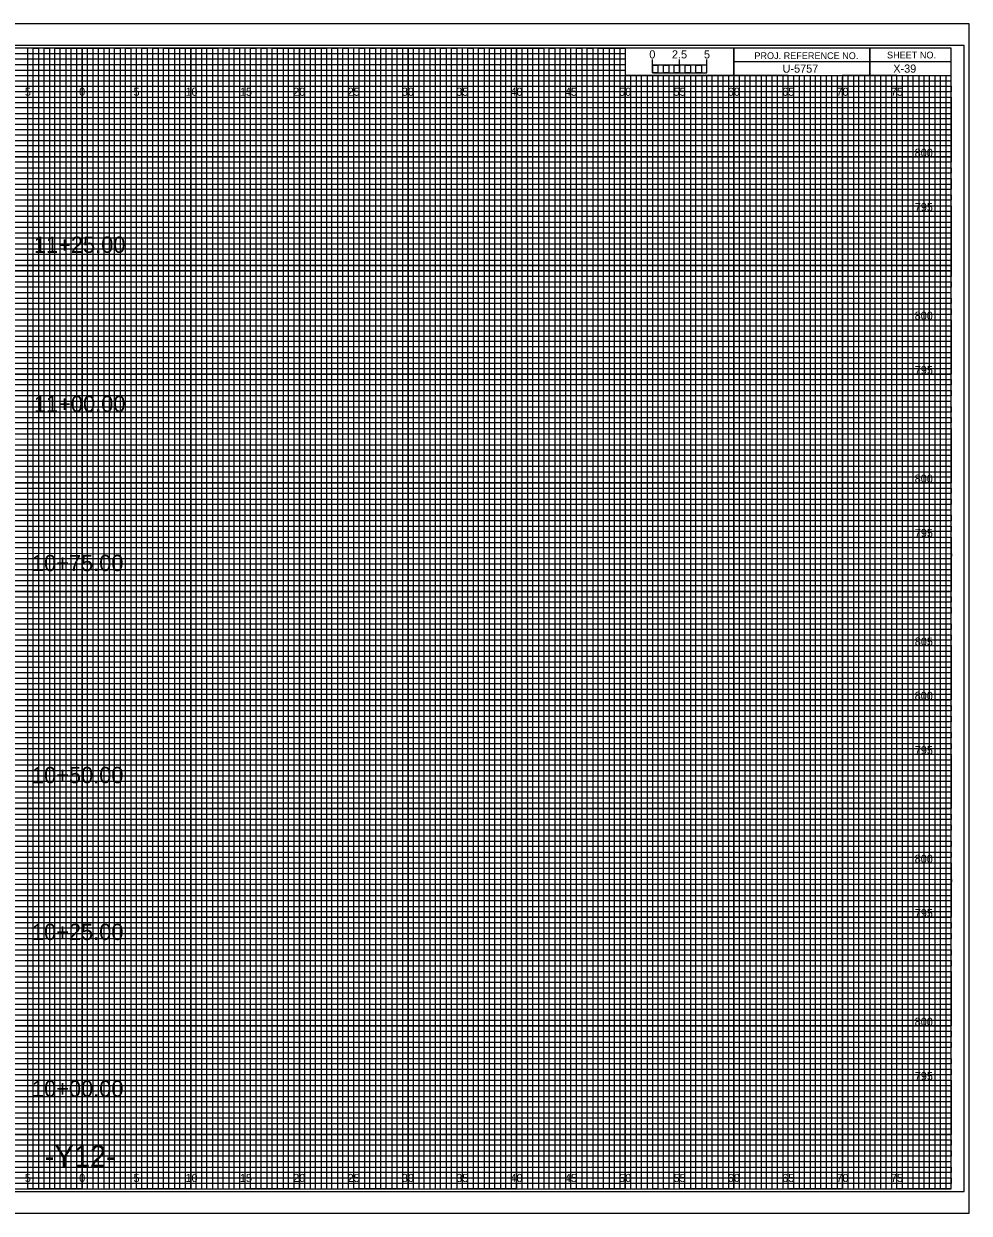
# Model space of a CAD drawing. Extents: x -7 to 162, y -2 to 107.
# Drawn here: x 74.6 to 161.7, y -2.3 to 107.3 of the extents above; entities that cross this region are included whole.
import ezdxf

# ---------------------------------------------------------------- set-up
doc = ezdxf.new("R2010")
doc.units = 0
for name, color, linetype in [('Exist Cross Section Cell', 7, 'Continuous'), ('Exist XS Center Line Elevation Label', 7, 'Continuous'), ('Prop CMT Pvmt Course 2 Wedge', 7, 'Continuous'), ('Prop CMT Shld Paved Course 3', 7, 'Continuous'), ('Prop XS Alignment Label', 7, 'Continuous'), ('Prop XS Bar Scale Labels', 7, 'Continuous'), ('Prop XS Elevation Labels', 7, 'Continuous'), ('Prop XS Hydro Elevations', 7, 'Continuous'), ('Prop XS Project Number', 7, 'Continuous'), ('Prop XS SE Text', 7, 'Continuous'), ('Prop XS Sheet Number', 7, 'Continuous'), ('Prop XS Side Slope Text', 7, 'Continuous'), ('Prop XS Station Labels', 7, 'Continuous'), ('Sheet Cross Section Grid Minor 2 CELL', 7, 'Continuous'), ('Sheet Cross Section Scale CELL', 7, 'Continuous'), ('Sheet DOT Grid CELL', 7, 'Continuous'), ('Sheet Plot Border Inside CELL', 7, 'Continuous')]:
    doc.layers.add(name, color=color, linetype=linetype)

msp = doc.modelspace()

# ---------------------------------------------------------------- linework, layer by layer
at = {"layer": 'Exist Cross Section Cell'}
for p, q in [((75, 105), (70, 105)), ((75, 0), (75, 105)), ((85, 105), (80, 105)), ((80, 105), (80, 0)), ((85, 0), (85, 105)), ((95, 105), (90, 105)), ((90, 105), (90, 0)), ((95, 0), (95, 105)), ((105, 105), (100, 105)), ((100, 105), (100, 0)), ((105, 0), (105, 105)), ((115, 105), (110, 105)), ((110, 105), (110, 0)), ((115, 0), (115, 105)), ((125, 105), (120, 105)), ((120, 105), (120, 0)), ((125, 0), (125, 105)), ((130, 105), (130, 0)), ((135, 0), (135, 102.5)), ((145, 102.5), (140, 102.5)), ((140, 102.5), (140, 0)), ((145, 0), (145, 102.5)), ((155, 102.5), (150, 102.5)), ((150, 102.5), (150, 0)), ((155, 0), (155, 102.5)), ((80, 0), (75, 0)), ((90, 0), (85, 0)), ((100, 0), (95, 0)), ((110, 0), (105, 0)), ((120, 0), (115, 0)), ((130, 0), (125, 0)), ((140, 0), (135, 0)), ((150, 0), (145, 0)), ((160, 0), (155, 0)), ((160, 0), (160, 0))]:
    msp.add_line(p, q, dxfattribs=at)
for points in [[(0, 100), (160, 100), (160, 95), (0, 95)], [(0, 90), (160, 90), (160, 85), (0, 85)], [(0, 80), (160, 80), (160, 75), (0, 75)], [(0, 70), (160, 70), (160, 65), (0, 65)], [(0, 60), (160, 60), (160, 55), (0, 55)], [(0, 50), (160, 50), (160, 45), (0, 45)], [(0, 40), (160, 40), (160, 35), (0, 35)], [(0, 30), (160, 30), (160, 25), (0, 25)], [(0, 20), (160, 20), (160, 15), (0, 15)], [(0, 10), (160, 10), (160, 5), (0, 5)]]:
    msp.add_lwpolyline(points, dxfattribs=at)
at = {"layer": 'Exist XS Center Line Elevation Label'}
for points in [[(72.5, 0), (77.5, 0), (77.5, 105), (82.5, 105), (82.5, 0), (87.5, 0), (87.5, 105), (92.5, 105), (92.5, 0), (97.5, 0), (97.5, 105), (102.5, 105), (102.5, 0), (107.5, 0), (107.5, 105), (112.5, 105), (112.5, 0), (117.5, 0), (117.5, 105), (122.5, 105), (122.5, 0), (127.5, 0), (127.5, 105), (129.97, 105), (130, 105), (130, 102.5), (132.5, 102.5), (132.5, 0), (137.5, 0), (137.5, 102.5), (142.5, 102.5), (142.5, 0), (147.5, 0), (147.5, 102.5), (152.5, 102.5), (152.5, 0), (157.5, 0), (157.5, 102.5)], [(0, 102.5), (137.5, 102.5)], [(0, 92.5), (160, 92.5), (160, 97.5), (0, 97.5)], [(0, 82.5), (160, 82.5), (160, 87.5), (0, 87.5)], [(0, 72.5), (160, 72.5), (160, 77.5), (0, 77.5)], [(0, 62.5), (160, 62.5), (160, 67.5), (0, 67.5)], [(0, 52.5), (160, 52.5), (160, 57.5), (0, 57.5)], [(0, 42.5), (160, 42.5), (160, 47.5), (0, 47.5)], [(0, 32.5), (160, 32.5), (160, 37.5), (0, 37.5)], [(0, 22.5), (160, 22.5), (160, 27.5), (0, 27.5)], [(0, 12.5), (160, 12.5), (160, 17.5), (0, 17.5)], [(0, 2.5), (160, 2.5), (160, 7.5), (0, 7.5)]]:
    msp.add_lwpolyline(points, dxfattribs=at)
at = {"layer": 'Prop CMT Pvmt Course 2 Wedge'}
for p, q in [((161.65, 107.25), (-6.7, 107.25)), ((-6.7, -2.25), (161.65, -2.25))]:
    msp.add_line(p, q, dxfattribs=at)
at = {"layer": 'Prop CMT Shld Paved Course 3'}
msp.add_lwpolyline([(-6.7, -2.25), (161.65, -2.25), (161.65, 107.25), (-6.7, 107.25)], close=True, dxfattribs=at)
at = {"layer": 'Prop XS Hydro Elevations'}
for p, q in [((152.5, 105), (152.5, 102.5)), ((152.5, 102.5), (152.5, 105)), ((160, 103.75), (140, 103.75)), ((140, 103.75), (140, 102.5)), ((140, 102.5), (160, 102.5))]:
    msp.add_line(p, q, dxfattribs=at)
for points in [[(160, 105), (0, 105), (0, 0), (160, 0)], [(140, 105), (130, 105), (130, 102.52), (140, 102.52)], [(160, 105), (140, 105), (140, 102.5), (160, 102.5)]]:
    msp.add_lwpolyline(points, close=True, dxfattribs=at)
at = {"layer": 'Prop XS Side Slope Text'}
for p, q in [((0, 104.5), (130, 104.5)), ((130, 104.5), (130, 103.99)), ((130, 103.99), (0, 103.99)), ((0, 103.5), (130, 103.5)), ((130, 102.95), (0, 102.95)), ((130, 103.5), (130, 102.95)), ((0, 102), (160, 102))]:
    msp.add_line(p, q, dxfattribs=at)
for points in [[(0, 101.5), (135, 101.5), (160, 101.5), (160, 101), (0, 101)], [(0, 100.5), (160, 100.5), (160, 99.5), (0, 99.5)], [(0, 99), (160, 99), (160, 98.5), (0, 98.49)], [(0, 98), (160, 98), (160, 97), (0, 97)], [(0, 96.5), (160, 96.5), (160, 96), (0, 96)], [(0, 95.5), (160, 95.5), (160, 94.5), (0, 94.5)], [(0, 94), (160, 94), (160, 93.5), (0, 93.5)], [(0, 93), (160, 93), (160, 92), (0, 92)], [(0, 91.5), (160, 91.5), (160, 91), (0, 91)], [(0, 90.5), (160, 90.5), (160, 89.5), (0, 89.5)], [(0, 89), (160, 89), (160, 88.5), (0, 88.5)], [(0, 88), (160, 88), (160, 86.98), (160, 86.5), (160, 86), (0, 86)], [(0, 87), (160, 87), (160, 86.5), (0, 86.5)], [(0, 85.5), (160, 85.5), (160, 84.5), (0, 84.52)], [(0, 84.52), (160, 84.5), (160, 84), (0, 84)], [(0, 83.5), (160, 83.5), (160, 83), (0, 83)], [(0, 82), (160, 82), (160, 81.5), (0, 81.5)], [(0, 81), (160, 81), (160, 80.5), (0, 80.5)], [(-0.04, 79.45), (160, 79.45), (160, 78.94), (-0.04, 78.94)], [(0, 78.5), (160, 78.5), (160, 78), (0, 78)], [(0, 77), (160, 77), (160, 76.5), (0, 76.5)], [(0, 76), (160, 76), (160, 75.5), (0, 75.5)], [(0, 74.5), (160, 74.5), (160, 74), (0, 74)], [(0, 73.5), (160, 73.5), (160, 73), (0, 73)], [(0, 72), (160, 72), (160, 71.5), (0, 71.5)], [(0, 71), (160, 71), (160, 70.5), (0, 70.5)], [(0, 69.5), (160, 69.5), (160, 68.99), (0, 69)], [(0, 68.5), (160, 68.5), (160, 68), (0, 68)], [(0, 67), (160, 67), (160, 66.5), (0, 66.5)], [(0, 66), (160, 66), (160, 65.5), (0, 65.5)], [(0, 64.5), (160, 64.5), (160, 64), (0, 64)], [(0, 63.5), (160, 63.5), (160, 63), (0, 63)], [(0, 62), (160, 62), (160, 61.5), (0, 61.5)], [(0, 61), (160, 61), (160, 60.5), (0, 60.5)], [(0, 59.5), (160, 59.5), (160, 59), (0, 59)], [(0, 58.5), (160.03, 58.45), (160, 58), (0, 58)], [(0, 57), (160, 57), (160, 56.5), (0, 56.5)], [(0, 56), (160, 56), (160, 55.5), (0, 55.5)], [(0, 54.5), (160, 54.5), (160, 54), (0, 54)], [(0, 53.5), (160, 53.5), (160, 53), (0, 53)], [(0, 52), (160, 52), (160, 51.5), (0, 51.5)], [(0, 51), (160, 51), (160, 50.5), (0, 50.5)], [(0, 49.5), (160, 49.5), (160, 49), (0, 49)], [(0, 48.5), (160, 48.5), (160, 48), (0, 48)], [(0, 47), (160, 47), (160, 46.5), (0, 46.5)], [(0, 46), (160, 46), (160, 45.5), (0, 45.5)], [(0, 44.5), (160, 44.5), (160, 44), (0, 44)], [(0, 43.5), (160, 43.5), (160, 43), (0, 43)], [(0, 42), (160, 42), (160, 41.5), (0, 41.5)], [(0, 41), (160, 41), (160, 40.5), (0, 40.5)], [(0, 39.5), (160, 39.5), (160, 38.99), (0, 39)], [(0, 38.5), (160, 38.5), (160, 38), (0, 38)], [(0, 37), (160, 37), (160, 36.5), (0, 36.5)], [(0, 36), (160, 36), (160, 35.5), (0, 35.5)], [(0, 34.5), (160, 34.5), (160, 34), (0, 34)], [(0, 33.5), (160, 33.5), (160, 33), (0, 33)], [(0, 32), (160, 32), (160, 31.5), (0, 31.5)], [(0, 31), (160, 31), (160, 30.5), (0, 30.5)], [(0, 29.5), (160, 29.5), (160, 29), (0, 29)], [(0, 28.5), (160.03, 28.46), (160, 28), (0, 28)], [(0, 27), (160, 27), (160, 26.5), (0, 26.5)], [(0, 26), (160, 26), (160, 25.5), (0, 25.5)], [(0, 24.5), (160, 24.5), (160, 24), (0, 24)], [(0, 23.5), (160, 23.5), (160, 23), (0, 23)], [(0, 22), (160, 22), (160, 21.5), (0, 21.5)], [(0, 21), (160, 21), (160, 20.5), (0, 20.5)], [(0, 19.5), (160, 19.5), (160, 19), (0, 19)], [(0, 18.5), (160, 18.5), (160, 18), (0, 18)], [(0, 17), (160, 17), (160, 16.5), (0, 16.5)], [(0, 16), (160, 16), (160, 15.5), (0, 15.5)], [(0, 14.5), (160, 14.5), (160, 14), (0, 14)], [(0, 13.5), (160, 13.5), (160, 13), (0, 13)], [(0, 12), (160, 12), (160, 11.5), (0, 11.5)], [(0, 11), (160, 11), (160, 10.5), (0, 10.5)], [(0, 9.5), (160, 9.5), (160, 9), (0, 9)], [(0, 8.5), (160, 8.5), (160, 8), (0, 8)], [(0, 7), (160, 7), (160, 6.5), (0, 6.5)], [(0, 6), (160, 6), (160, 5.5), (0, 5.5)], [(0, 4.5), (160, 4.5), (160, 4), (0, 4)], [(0, 3.5), (160, 3.5), (160, 3), (0, 3)], [(0, 2), (160, 2), (160, 1.5), (0, 1.5)], [(0, 1), (160, 1), (160, 0.5), (0, 0.5)]]:
    msp.add_lwpolyline(points, dxfattribs=at)
at = {"layer": 'Sheet Cross Section Grid Minor 2 CELL'}
for p, q in [((133.5, 102.5), (133, 102.5)), ((133, 102.5), (133, 0)), ((133.5, 0), (133.5, 102.5)), ((134.5, 102.5), (134, 102.5)), ((134, 102.5), (134, 0)), ((134.5, 0), (134.5, 102.5)), ((133, 0), (132.5, 0)), ((134, 0), (133.5, 0))]:
    msp.add_line(p, q, dxfattribs=at)
for points in [[(75, 0), (75.5, 0), (75.5, 105), (76, 105), (76, 0)], [(76, 0), (76.5, 0), (76.5, 105), (77, 105), (77, 0)], [(77.5, 0), (78, 0), (78, 105), (78.5, 105), (78.5, 0)], [(78.5, 0), (79, 0), (79, 105), (79.5, 105), (79.5, 0)], [(80, 0), (80.5, 0), (80.5, 105), (81, 105), (81, 0)], [(81, 0), (81.5, 0), (81.5, 105), (82, 105), (82, 0)], [(82.5, 0), (83, 0), (83, 105), (83.5, 105), (83.5, 0)], [(83.5, 0), (84, 0), (84, 105), (84.5, 105), (84.5, 0)], [(85, 0), (85.5, 0), (85.5, 105), (86, 105), (86, 0)], [(86, 0), (86.5, 0), (86.5, 105), (87, 105), (87, 0)], [(87.5, 0), (88, 0), (88, 105), (88.5, 105), (88.5, 0)], [(88.5, 0), (89, 0), (89, 105), (89.5, 105), (89.5, 0)], [(90, 0), (90.5, 0), (90.5, 105), (91, 105), (91, 0)], [(91, 0), (91.5, 0), (91.5, 105), (92, 105), (92, 0)], [(92.5, 0), (93, 0), (93, 105), (93.5, 105), (93.5, 0)], [(93.5, 0), (94, 0), (94, 105), (94.5, 105), (94.5, 0)], [(95, 0), (95.5, 0), (95.5, 105), (96, 105), (96, 0)], [(96, 0), (96.5, 0), (96.5, 105), (97, 105), (97, 0)], [(97.5, 0), (98, 0), (98, 105), (98.5, 105), (98.5, 0)], [(98.5, 0), (99, 0), (99, 105), (99.5, 105), (99.5, 0)], [(100, 0), (100.5, 0), (100.5, 105), (101, 105), (101, 0)], [(101, 0), (101.5, 0), (101.5, 105), (102, 105), (102, 0)], [(102.5, 0), (103, 0), (103, 105), (103.5, 105), (103.5, 0)], [(103.5, 0), (104, 0), (104, 105), (104.5, 105), (104.5, 0)], [(105, 0), (105.5, 0), (105.5, 105), (106, 105), (106, 0)], [(106, 0), (106.5, 0), (106.5, 105), (107, 105), (107, 0)], [(107.5, 0), (108, 0), (108, 105), (108.5, 105), (108.5, 0)], [(108.5, 0), (109, 0), (109, 105), (109.5, 105), (109.5, 0)], [(110, 0), (110.5, 0), (110.5, 105), (111, 105), (111, 0)], [(111, 0), (111.5, 0), (111.5, 105), (112, 105), (112, 0)], [(112.5, 0), (113, 0), (113, 105), (113.5, 105), (113.5, 0)], [(113.5, 0), (114, 0), (114, 105), (114.5, 105), (114.5, 0)], [(115, 0), (115.5, 0), (115.5, 105), (116, 105), (116, 0)], [(116, 0), (116.5, 0), (116.5, 105), (117, 105), (117, 0)], [(117.5, 0), (118, 0), (118, 105), (118.5, 105), (118.5, 0)], [(118.5, 0), (119, 0), (119, 105), (119.5, 105), (119.5, 0)], [(120, 0), (120.5, 0), (120.5, 105), (121, 105), (121, 0)], [(121, 0), (121.5, 0), (121.5, 105), (122, 105), (122, 0)], [(122.5, 0), (123, 0), (123, 105), (123.5, 105), (123.5, 0)], [(123.5, 0), (124, 0), (124, 105), (124.5, 105), (124.5, 0)], [(125, 0), (125.5, 0), (125.5, 105), (126, 105), (126, 0)], [(126, 0), (126.5, 0), (126.5, 105), (127, 105), (127, 0)], [(127.5, 0), (128, 0), (128, 105), (128.5, 105), (128.5, 0)], [(128.5, 0), (129, 0), (129, 105), (129.5, 105), (129.5, 0)], [(130, 0), (130.5, 0), (130.5, 102.5), (131.01, 102.5), (131.01, 0)], [(131, 0), (131.5, 0), (131.5, 102.5), (132, 102.5), (132, 0)], [(135, 0), (135.49, 0), (135.49, 102.5), (136, 102.5), (136, 0)], [(136, 0), (136.5, 0), (136.5, 102.5), (137.03, 102.5), (137.03, 0)], [(137.5, 0), (138, 0), (138, 102.5), (138.5, 102.5), (138.5, 0)], [(138.5, 0), (139, 0), (139, 102.5), (139.5, 102.5), (139.5, 0)], [(140, 0), (140.5, 0), (140.5, 102.5), (141, 102.5), (141, 0)], [(141, 0), (141.5, 0), (141.5, 102.5), (142, 102.5), (142, 0)], [(142.5, 0), (143, 0), (143, 102.5), (143.5, 102.5), (143.5, 0)], [(143.5, 0), (144, 0), (144, 102.5), (144.5, 102.5), (144.5, 0)], [(145, 0), (145.5, 0), (145.5, 102.5), (146, 102.5), (146, 0)], [(146, 0), (146.5, 0), (146.5, 102.5), (147, 102.5), (147, 0)], [(147.5, 0), (148, 0), (148, 102.5), (148.5, 102.5), (148.5, 0)], [(148.5, 0), (149, 0), (149, 102.5), (149.5, 102.5), (149.5, 0)], [(150, 0), (150.5, 0), (150.5, 102.5), (151, 102.5), (151, 0)], [(151, 0), (151.5, 0), (151.5, 102.5), (152, 102.5), (152, 0)], [(152.5, 0), (153, 0), (153, 102.5), (153.5, 102.5), (153.5, 0)], [(153.5, 0), (154, 0), (154, 102.5), (154.5, 102.5), (154.5, 0)], [(155, 0), (155.5, 0), (155.5, 102.5), (156, 102.5), (156, 0)], [(156, 0), (156.5, 0), (156.5, 102.5), (157, 102.5), (157, 0)], [(157.5, 0), (158, 0), (158, 102.5), (158.5, 102.5), (158.5, 0)], [(158.5, 0), (159, 0), (159, 102.5), (159.5, 102.5), (159.5, 0)]]:
    msp.add_lwpolyline(points, dxfattribs=at)
at = {"layer": 'Sheet Cross Section Scale CELL'}
for p, q in [((132.5, 102.75), (132.5, 103.95)), ((132.5, 103.45), (132.5, 103.95)), ((135, 102.75), (135, 103.95)), ((137.5, 102.75), (137.5, 103.95)), ((137.5, 103.45), (137.5, 103.95))]:
    msp.add_line(p, q, dxfattribs=at)
for points in [[(137.5, 103.45), (132.5, 103.45), (132.5, 102.75), (137.5, 102.75)], [(132.5, 103.45), (133, 103.45), (133, 102.75), (132.5, 102.75)], [(133.5, 103.45), (134, 103.45), (134, 102.75), (133.5, 102.75)], [(134.5, 103.45), (135, 103.45), (135, 102.75), (134.5, 102.75)], [(135.5, 103.45), (136, 103.45), (136, 102.75), (135.5, 102.75)], [(136.5, 103.45), (137, 103.45), (137, 102.75), (136.5, 102.75)]]:
    msp.add_lwpolyline(points, close=True, dxfattribs=at)
at = {"layer": 'Sheet DOT Grid CELL'}
for p, q in [((75, 0), (75, 105)), ((80, 0), (80, 105)), ((85, 0), (85, 105)), ((90, 0), (90, 105)), ((95, 0), (95, 105)), ((100, 0), (100, 105)), ((105, 0), (105, 105)), ((110, 0), (110, 105)), ((115, 0), (115, 105)), ((120, 0), (120, 105)), ((125, 0), (125, 105)), ((130, 0), (130, 102.34)), ((135, 0), (135, 102.34)), ((140, 0), (140, 102.34)), ((145, 0), (145, 102.34)), ((150, 0), (150, 102.34)), ((155, 0), (155, 102.34)), ((0, 100), (160, 100)), ((0, 95), (160, 95)), ((0, 90), (160, 90)), ((0, 85), (160, 85)), ((0, 80), (160, 80)), ((0, 75), (160, 75)), ((0, 70), (160, 70)), ((0, 65), (160, 65)), ((0, 60), (160, 60)), ((0, 55), (160, 55)), ((0, 50), (160, 50)), ((0, 45), (160, 45)), ((0, 40), (160, 40)), ((0, 35), (160, 35)), ((0, 30), (160, 30)), ((0, 25), (160, 25)), ((0, 20), (160, 20)), ((0, 15), (160, 15)), ((0, 10), (160, 10)), ((0, 5), (160, 5))]:
    msp.add_line(p, q, dxfattribs=at)
at = {"layer": 'Sheet Plot Border Inside CELL'}
msp.add_lwpolyline([(-5.4, -0.25), (161.2, -0.25), (161.2, 105.25), (-5.4, 105.25)], close=True, dxfattribs=at)

# ---------------------------------------------------------------- texts
at = {"layer": 'Prop XS Alignment Label'}
msp.add_text('-Y12-', height=2, dxfattribs=at).set_placement((76.57, 2))
at = {"layer": 'Prop XS Bar Scale Labels'}
for s, p in [('2.5', (134.29, 104.06)), ('5', (137.24, 104.06))]:
    msp.add_text(s, height=0.75, dxfattribs=at).set_placement(p)
at = {"layer": 'Prop XS Elevation Labels'}
for s, p in [('800', (156.63, 95)), ('795', (156.64, 90)), ('800', (156.63, 80)), ('795', (156.64, 75)), ('800', (156.63, 65)), ('795', (156.64, 60)), ('805', (156.64, 50)), ('800', (156.63, 45)), ('795', (156.64, 40)), ('800', (156.63, 30)), ('795', (156.64, 25)), ('800', (156.63, 15)), ('795', (156.64, 10))]:
    msp.add_text(s, height=0.75, dxfattribs=at).set_placement(p)
at = {"layer": 'Prop XS Hydro Elevations'}
for s, p in [('PROJ. REFERENCE NO.', (141.88, 104)), ('SHEET NO.', (154.09, 104.06))]:
    msp.add_text(s, height=0.625, dxfattribs=at).set_placement(p)
at = {"layer": 'Prop XS Project Number'}
msp.add_text('U-5757', height=0.75, dxfattribs=at).set_placement((144.47, 102.75))
at = {"layer": 'Prop XS SE Text'}
for s, p in [('5', (74.74, 100.62)), ('0', (79.73, 100.62)), ('0', (79.73, 100.62)), ('5', (84.74, 100.62)), ('10', (89.52, 100.62)), ('15', (94.53, 100.62)), ('20', (99.43, 100.62)), ('25', (104.44, 100.62)), ('30', (109.43, 100.62)), ('35', (114.44, 100.62)), ('40', (119.43, 100.62)), ('45', (124.44, 100.62)), ('50', (129.43, 100.62)), ('55', (134.44, 100.62)), ('60', (139.43, 100.62)), ('65', (144.44, 100.62)), ('70', (149.43, 100.62)), ('75', (154.44, 100.62)), ('5', (74.74, 0.62)), ('0', (79.73, 0.62)), ('0', (79.73, 0.62)), ('5', (84.74, 0.62)), ('10', (89.52, 0.62)), ('15', (94.53, 0.62)), ('20', (99.43, 0.62)), ('25', (104.44, 0.62)), ('30', (109.43, 0.62)), ('35', (114.44, 0.62)), ('40', (119.43, 0.62)), ('45', (124.44, 0.62)), ('50', (129.43, 0.62)), ('55', (134.44, 0.62)), ('60', (139.43, 0.62)), ('65', (144.44, 0.62)), ('70', (149.43, 0.62)), ('75', (154.44, 0.62))]:
    msp.add_text(s, height=0.75, dxfattribs=at).set_placement(p)
at = {"layer": 'Prop XS Sheet Number'}
msp.add_text('X-39', height=0.75, dxfattribs=at).set_placement((154.66, 102.75))
at = {"layer": 'Prop XS Station Labels'}
for s, p in [('11+25.00', (75.57, 86.16)), ('11+00.00', (75.57, 71.51)), ('10+75.00', (75.39, 56.86)), ('10+50.00', (75.39, 37.34)), ('10+25.00', (75.39, 22.9)), ('10+00.00', (75.39, 8.47))]:
    msp.add_text(s, height=1.5, dxfattribs=at).set_placement(p)
at = {"layer": 'Sheet Cross Section Scale CELL'}
msp.add_text('0', height=0.75, dxfattribs=at).set_placement((132.21, 104.06))

doc.saveas('drawing.dxf')
